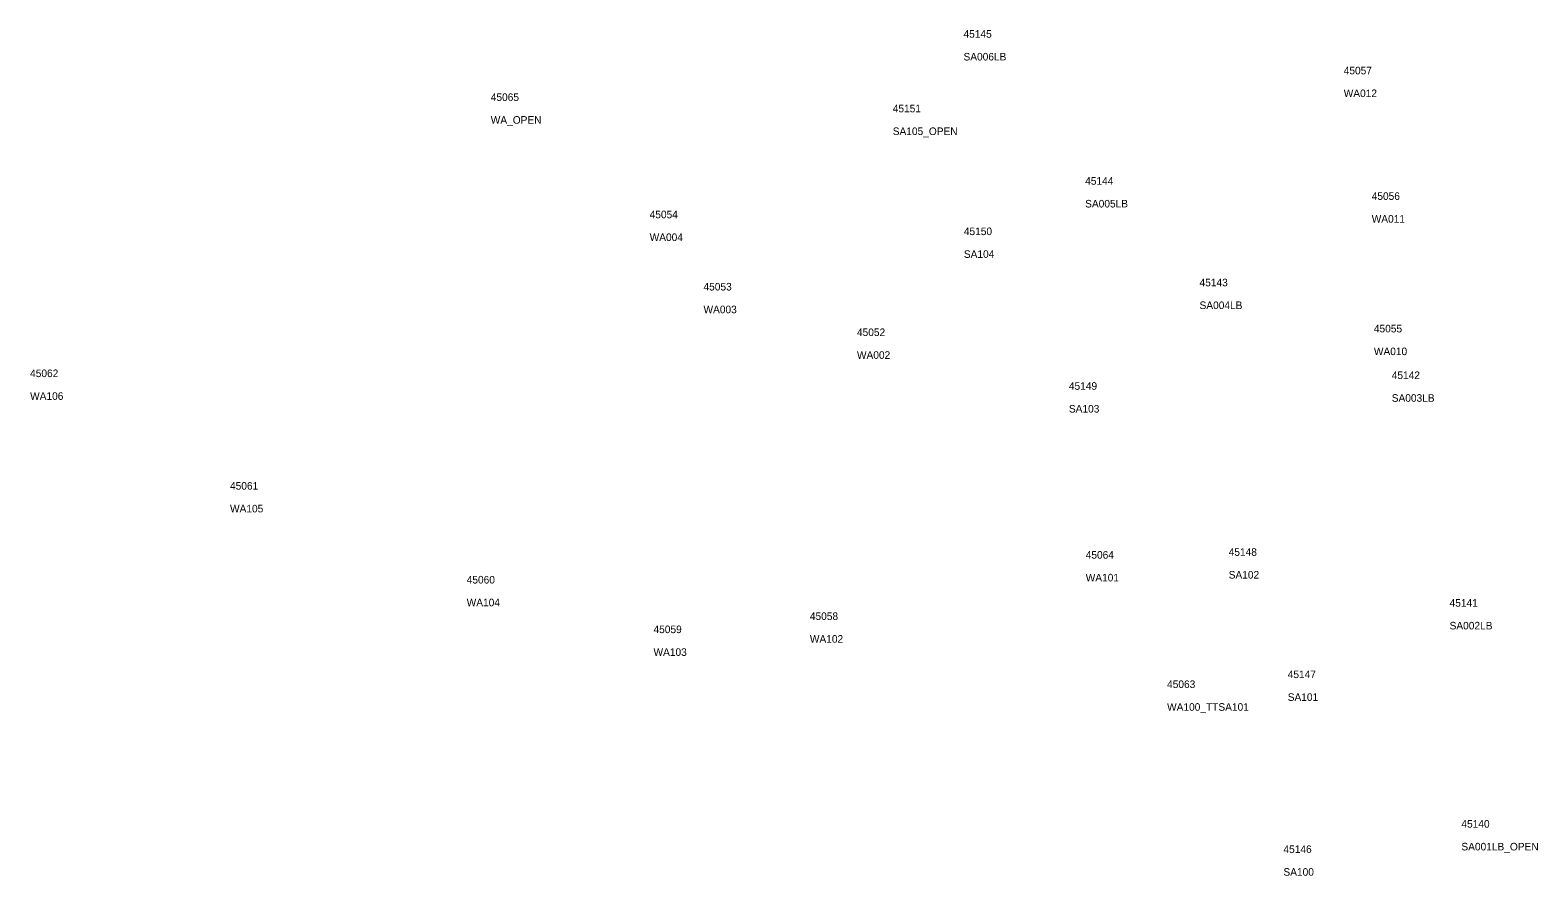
# Model space of a CAD drawing. Extents: x 1503676 to 1665494, y 654328 to 989038.
# Drawn here: x 1612066.2 to 1612562.9, y 722627.6 to 722906.3 of the extents above; entities that cross this region are included whole.
import ezdxf

# ---------------------------------------------------------------- set-up
doc = ezdxf.new("R2010")
doc.units = 0
for name, color, linetype in [('Level 14', 7, 'Continuous'), ('Level 17', 7, 'Continuous'), ('Level 18', 7, 'Continuous'), ('Level 19', 7, 'Continuous')]:
    doc.layers.add(name, color=color, linetype=linetype)

msp = doc.modelspace()

# ---------------------------------------------------------------- texts
at = {"layer": 'Level 14'}
for s, p in [('45057', (1612498.97, 722891.76)), ('45065', (1612217.94, 722882.98)), ('45056', (1612508.19, 722850.38)), ('45054', (1612270.29, 722844.33)), ('45053', (1612288.03, 722820.53)), ('45052', (1612338.59, 722805.51)), ('45055', (1612508.91, 722806.72)), ('45062', (1612066.16, 722791.99)), ('45061', (1612132.03, 722754.91)), ('45064', (1612413.96, 722732.16)), ('45060', (1612210.01, 722723.97)), ('45058', (1612323.08, 722711.96)), ('45059', (1612271.56, 722707.63)), ('45063', (1612440.77, 722689.54))]:
    msp.add_text(s, height=2.5, dxfattribs=at).set_placement(p)
at = {"layer": 'Level 17'}
for s, p in [('WA012', (1612498.97, 722884.26)), ('WA_OPEN', (1612217.94, 722875.48)), ('WA011', (1612508.19, 722842.88)), ('WA004', (1612270.29, 722836.83)), ('WA003', (1612288.03, 722813.03)), ('WA002', (1612338.59, 722798.01)), ('WA010', (1612508.91, 722799.22)), ('WA106', (1612066.16, 722784.49)), ('WA105', (1612132.03, 722747.41)), ('WA101', (1612413.96, 722724.66)), ('WA104', (1612210.01, 722716.47)), ('WA102', (1612323.08, 722704.46)), ('WA103', (1612271.56, 722700.13)), ('WA100_TTSA101', (1612440.77, 722682.04))]:
    msp.add_text(s, height=2.5, dxfattribs=at).set_placement(p)
at = {"layer": 'Level 18'}
for s, p in [('SA006LB', (1612373.7, 722896.32)), ('SA105_OPEN', (1612350.38, 722871.75)), ('SA005LB', (1612413.78, 722847.88)), ('SA104', (1612373.81, 722831.28)), ('SA004LB', (1612451.47, 722814.41)), ('SA103', (1612408.42, 722780.31)), ('SA003LB', (1612514.79, 722783.86)), ('SA102', (1612461.07, 722725.6)), ('SA002LB', (1612533.85, 722708.84)), ('SA101', (1612480.52, 722685.3)), ('SA001LB_OPEN', (1612537.74, 722636.02)), ('SA100', (1612479.11, 722627.68))]:
    msp.add_text(s, height=2.5, dxfattribs=at).set_placement(p)
at = {"layer": 'Level 19'}
for s, p in [('45145', (1612373.7, 722903.82)), ('45151', (1612350.38, 722879.25)), ('45144', (1612413.78, 722855.38)), ('45150', (1612373.81, 722838.78)), ('45143', (1612451.47, 722821.91)), ('45142', (1612514.79, 722791.36)), ('45149', (1612408.42, 722787.81)), ('45148', (1612461.07, 722733.1)), ('45141', (1612533.85, 722716.34)), ('45147', (1612480.52, 722692.8)), ('45140', (1612537.74, 722643.52)), ('45146', (1612479.11, 722635.18))]:
    msp.add_text(s, height=2.5, dxfattribs=at).set_placement(p)

doc.saveas('drawing.dxf')
